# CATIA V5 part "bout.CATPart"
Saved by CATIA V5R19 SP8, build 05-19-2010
Part number: bout
Bounding box of the stored display mesh (mm): x -59.371 to 38.294, y 0 to 29, z -147.742 to 229.605
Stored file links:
  G:\EU_thinkMotion\CFAO_2010\SIL_groupe1\SIL_groupe1\A reprendre\fbruguiere\fbruguiere\fbruguiere\bout.CATPart
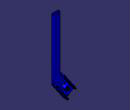
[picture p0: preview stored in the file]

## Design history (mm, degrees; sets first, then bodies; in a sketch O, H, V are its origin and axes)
Body1 (main body)
  Sketch1 on zx-plane, origin (0, 0, 0), H (-1, 0, 0), V (0, 0, 1)
    line L1 (-38.2935, 229.6045) -> (-8.2935, 229.6045)
    line L2 (-8.2935, 229.6045) -> (-8.2935, -20.3955)
    line L3 (-38.2935, 32.7491) -> (-38.2935, 229.6045)
    line L4 (-8.2935, -20.3955) -> (59.371, -119.5606)
    line L5 (-38.2935, 32.7491) -> (-38.2935, -65.1396)
    line L6 (-38.2935, -65.1396) -> (18.0697, -147.7422)
    line L7 (59.371, -119.5606) -> (18.0697, -147.7422)
    length L7 = 50
    length L2 = 250
    length L6 = 100
    length L1 = 30
    horizontal: L1 H
    vertical: L2 V, L3 V, L5 V
    parallelism: L6 L4
    perpendicularity: L7 L6
  Pad1: profile Sketch1, direction (0, 1, 0), length 20
  Sketch2 on end face of Pad1, origin (0, 20, 0), H (-1, 0, 0), V (0, 0, 1)
  Sketch3 on end face of Pad1, origin (0, 20, 0), H (-1, 0, 0), V (0, 0, 1)
    line L1 (57.2044, -123.8073) -> (-0.9365, -39.8461)
    line L2 (-0.9365, -39.8461) -> (7.3072, -34.1376)
    line L3 (7.3072, -34.1376) -> (7.3072, 251.401)
    line L4 (7.3072, 251.401) -> (-64.0574, 251.401)
    line L5 (-64.0574, 251.401) -> (-64.0574, -63.556)
    line L6 (-64.0574, -63.556) -> (-37.7265, -65.3222)
    point P7 (-37.7265, -65.3222)
    line L7 (-37.7265, -65.3222) -> (-33.8216, -62.6182)
    line L8 (-33.8216, -62.6182) -> (23.383, -145.2273)
    line L9 (23.383, -145.2273) -> (24.3192, -146.5793)
    line L10 (24.3192, -146.5793) -> (57.2044, -123.8073)
    length L10 = 40
    perpendicularity: L2 L1
    vertical: L3 V, L5 V
    horizontal: L4 H
    coincidence: P7 L2
    parallelism: L7 L2, L8 L1, L9 L8, L10 L2
  Pocket1: profile Sketch3, direction (0, -1, 0), length 11
  Sketch4 on end face of Pocket1, origin (0, 9, 0), H (-1, 0, 0), V (0, 0, 1)
    circle A1 centre (8.1688, -88.1258) radius 10
    point P1 (8.1688, -88.1258)
    reference projected line E1 (-33.8216, -62.6182) -> (22.8607, -144.4731) from edge [end face of Pad1 | face of Pocket1 from Sketch3.L8]
    reference projected line E2 (55.9025, -121.9273) -> (-0.9365, -39.8461) from edge [end face of Pad1 | face of Pocket1 from Sketch3.L1]
    reference projected line E3 (55.9025, -121.9273) -> (-0.9365, -39.8461) from edge [end face of Pad1 | face of Pocket1 from Sketch3.L1]
    radius A1 = 10
    distance E1 E2 = 40 (reference)
    distance P1 E3 = 20
  Pad2: profile Sketch4, direction (0, 1, 0), length 20
  Sketch5 on end face of Pad2, origin (0, 29, 0), H (-1, 0, 0), V (0, 0, 1)
    circle A1 centre (8.2333, -88.0799) radius 5
    radius A1 = 5
  Pocket2: profile Sketch5, direction (0, -1, 0), through (limit type 6)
